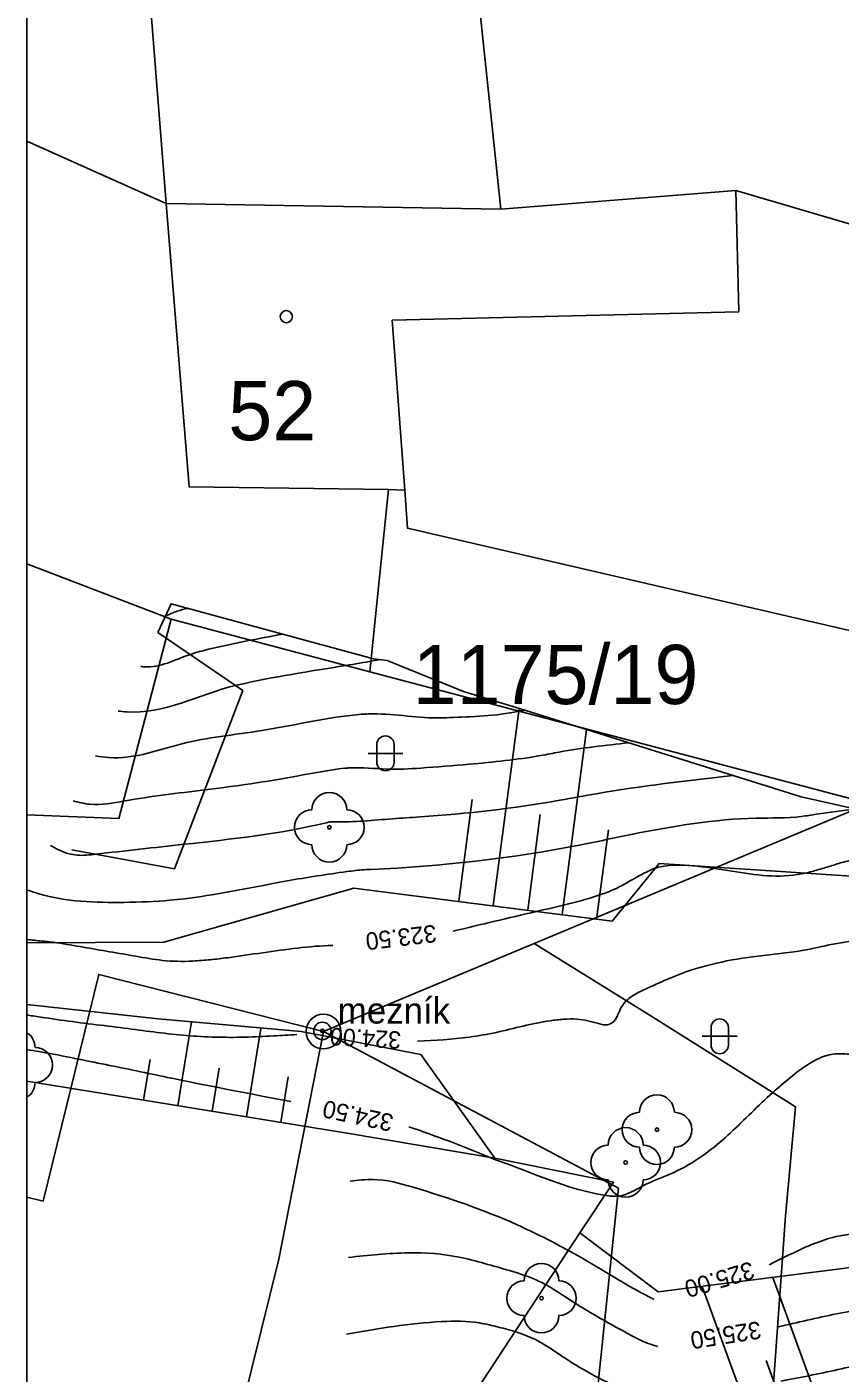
# Model space of a CAD drawing. Extents: x -564043 to -563833, y -1163561 to -1163412.
# Drawn here: x -564043.05 to -564019.66, y -1163509.03 to -1163470.35 of the extents above; entities that cross this region are included whole.
import ezdxf

# ---------------------------------------------------------------- set-up
doc = ezdxf.new("R2010")
doc.units = 0
for name, color, linetype in [('_rám PH1 a PH3', 7, 'Continuous'), ('Hranice parcel', 7, 'Continuous'), ('Parcelní čísla', 7, 'Continuous'), ('Vnitřní kresba', 7, 'Continuous'), ('Vrstva 14', 7, 'Continuous'), ('Vrstva 22', 7, 'Continuous'), ('Vrstva 24', 7, 'Continuous'), ('Vrstva 25', 7, 'Continuous'), ('Vrstva 26', 7, 'Continuous'), ('Vrstva 41', 7, 'Continuous'), ('Vrstva 48', 7, 'Continuous'), ('Značky bodu BP', 7, 'Continuous'), ('Značky budov', 7, 'Continuous')]:
    doc.layers.add(name, color=color, linetype=linetype)

msp = doc.modelspace()

# ---------------------------------------------------------------- linework, layer by layer
at = {"layer": '_rám PH1 a PH3'}
msp.add_line((-564043.046, -1163412.494), (-564043.046, -1163560.994), dxfattribs=at)
at = {"layer": 'Hranice parcel'}
for p, q in [((-564040.63, -1163455.19), (-564039.04, -1163475.43)), ((-564043.046, -1163473.637), (-564039.04, -1163475.43)), ((-564032.65, -1163483.65), (-564033.19, -1163488.88)), ((-564033.19, -1163488.88), (-564038.9, -1163487.37)), ((-564018.83, -1163492.67), (-564033.19, -1163488.88)), ((-564028.46, -1163496.69), (-564018.83, -1163492.67)), ((-564034.52, -1163499.22), (-564028.46, -1163496.69))]:
    msp.add_line(p, q, dxfattribs=at)
for points in [[(-564039.04, -1163475.43), (-564029.42, -1163475.59), (-564022.66, -1163475.05), (-564001.49, -1163481.27)], [(-564039.04, -1163475.43), (-564038.38, -1163483.57), (-564032.65, -1163483.65)], [(-564032.65, -1163483.65), (-564032.18, -1163483.66), (-564032.1, -1163484.76), (-564017.32, -1163488.18), (-564018.83, -1163492.67)], [(-564038.9, -1163487.37), (-564043.046, -1163485.784)], [(-564043.046, -1163492.996), (-564040.4, -1163493.1), (-564038.9, -1163487.37)], [(-564028.46, -1163496.69), (-564025.15, -1163498.74), (-564020.95, -1163501.38), (-564021.23, -1163504.52), (-564021.9, -1163513.74)], [(-564034.52, -1163499.22), (-564040.98, -1163497.58), (-564042.58, -1163504.09), (-564043.046, -1163503.975)], [(-564037.34, -1163511.95), (-564035.8, -1163505.76), (-564034.52, -1163499.22)], [(-564033.84, -1163535.6), (-564027.54, -1163518.14), (-564026.04, -1163503.72), (-564034.52, -1163499.22)]]:
    msp.add_lwpolyline(points, dxfattribs=at)
at = {"layer": 'Vnitřní kresba'}
for p, q in [((-564030.92, -1163461.24), (-564029.42, -1163475.59)), ((-564022.58, -1163478.54), (-564022.66, -1163475.05)), ((-564032.54, -1163478.78), (-564022.58, -1163478.54)), ((-564032.54, -1163478.78), (-564032.18, -1163483.66))]:
    msp.add_line(p, q, dxfattribs=at)
at = {"layer": 'Vrstva 14'}
for points in [[(-564033.08, -1163488.51), (-564038.9, -1163486.93), (-564039.28, -1163487.75)], [(-564039.28, -1163487.75), (-564036.84, -1163489.42), (-564038.8, -1163494.54), (-564041.75, -1163494)], [(-564032.69, -1163488.56), (-564033.08, -1163488.51)], [(-564005.7, -1163491.6), (-564006.2, -1163491.58), (-564012.27, -1163492.36), (-564018.09, -1163493.08), (-564020.78, -1163492.48), (-564028.85, -1163489.95), (-564030.49, -1163489.45), (-564032.69, -1163488.56)], [(-564027.15, -1163505), (-564024.9, -1163506.7), (-564019.59, -1163506.03), (-564017.25, -1163505.67), (-564014.46, -1163504.32), (-564008.13, -1163500.82), (-564005.74, -1163499.66), (-563997.05, -1163495.87), (-563995.48, -1163492.66)], [(-564043.046, -1163496.675), (-564039.11, -1163496.65), (-564033.65, -1163495.1), (-564026.22, -1163496.05), (-564024.87, -1163494.39), (-564018.75, -1163494.79), (-564015.5, -1163495.09), (-564011.97, -1163494.31)], [(-564043.046, -1163498.44), (-564039.27, -1163498.85), (-564035.16, -1163499.22), (-564031.72, -1163499.88), (-564029.59, -1163502.86)], [(-564043.046, -1163500.646), (-564033.72, -1163502.16), (-564029.59, -1163502.86), (-564026.18, -1163503.55), (-564027.15, -1163505), (-564030.15, -1163509.57), (-564034.03, -1163515.15), (-564041.74, -1163526.9)]]:
    msp.add_lwpolyline(points, dxfattribs=at)
at = {"layer": 'Vrstva 22'}
for centre in [(-564034.35, -1163493.35), (-564024.93, -1163502.04), (-564025.83, -1163502.98), (-564028.25, -1163506.88)]:
    msp.add_circle(centre, 0.05, dxfattribs=at)
for centre, start, end in [((-564034.35, -1163492.85), 0, 180), ((-564034.85, -1163493.35), 90, 270), ((-564033.85, -1163493.35), 270, 90), ((-564034.35, -1163493.85), 180, 0), ((-564043.31, -1163499.68), 0, 58.0739), ((-564042.81, -1163500.18), 270, 90), ((-564043.31, -1163500.68), 301.9261, 0), ((-564024.93, -1163501.54), 0, 180), ((-564025.43, -1163502.04), 90, 270), ((-564024.43, -1163502.04), 270, 90), ((-564025.83, -1163502.48), 0, 180), ((-564026.33, -1163502.98), 90, 270), ((-564024.93, -1163502.54), 180, 0), ((-564025.33, -1163502.98), 270, 90), ((-564025.83, -1163503.48), 180, 0), ((-564028.25, -1163506.38), 0, 180), ((-564028.75, -1163506.88), 90, 270), ((-564027.75, -1163506.88), 270, 90), ((-564028.25, -1163507.38), 180, 0)]:
    msp.add_arc(centre, 0.5, start, end, dxfattribs=at)
at = {"layer": 'Vrstva 24'}
for radius in [0.25, 0.05]:
    msp.add_circle((-564034.55, -1163499.2), radius, dxfattribs=at)
for points in [[(-564040.42, -1163490.01), (-564040.184, -1163490.036), (-564037.051, -1163489.276), (-564036.974, -1163489.258), (-564033.879, -1163488.703), (-564033.095, -1163488.569), (-564032.88, -1163488.53)], [(-564041.72, -1163492.59), (-564041.232, -1163492.69), (-564040.244, -1163492.595), (-564037.934, -1163492.277), (-564035.281, -1163491.88), (-564033.905, -1163491.655), (-564033.758, -1163491.643), (-564032.696, -1163491.679), (-564031.72, -1163491.649), (-564030.331, -1163491.539), (-564028.273, -1163491.289), (-564027.738, -1163491.19), (-564025.74, -1163490.92)], [(-564043.01, -1163495.16), (-564042.704, -1163495.259), (-564040.249, -1163495.507), (-564038.933, -1163495.447), (-564035.565, -1163494.892), (-564033.841, -1163494.623), (-564033.354, -1163494.57), (-564033.147, -1163494.56), (-564027.164, -1163493.861), (-564025.624, -1163493.548), (-564022.084, -1163493.089), (-564020.777, -1163493.039), (-564020.345, -1163492.975), (-564019.205, -1163492.831), (-564014.698, -1163492.66), (-564013.156, -1163492.656), (-564012.231, -1163492.615), (-564007.86, -1163491.79)], [(-564031.812, -1163499.5), (-564030.324, -1163499.377), (-564029.547, -1163499.242), (-564028.773, -1163499.061), (-564028.001, -1163498.908), (-564027.615, -1163498.867), (-564027.23, -1163498.862), (-564026.607, -1163498.989), (-564026.346, -1163499.024), (-564026.173, -1163498.931), (-564026.053, -1163498.733), (-564025.945, -1163498.506), (-564025.804, -1163498.324), (-564025.519, -1163498.129), (-564024.955, -1163497.86), (-564024.387, -1163497.614), (-564023.213, -1163497.254), (-564022.022, -1163497.051), (-564020.757, -1163496.892), (-564019.862, -1163496.708), (-564018.98, -1163496.594), (-564018.537, -1163496.592), (-564018.102, -1163496.651), (-564017.139, -1163496.933), (-564016.188, -1163497.257), (-564015.239, -1163497.589), (-564014.283, -1163497.894), (-564013.587, -1163498.092), (-564013.3, -1163498.155), (-564013.009, -1163498.205), (-564012.719, -1163498.253), (-564012.43, -1163498.312), (-564010.133, -1163499.025), (-564009.7, -1163499.224), (-564009.288, -1163499.466), (-564008.873, -1163499.71), (-564008.431, -1163499.916), (-564006.88, -1163500.213), (-564005.699, -1163500.108), (-564005.367, -1163500.004), (-564005.352, -1163499.957), (-564005.385, -1163499.904), (-564005.432, -1163499.847), (-564005.458, -1163499.79), (-564005.454, -1163499.732), (-564005.373, -1163499.663), (-564004.291, -1163498.6), (-564003.237, -1163497.506), (-564002.153, -1163496.417), (-564001.583, -1163495.886), (-564000.985, -1163495.371), (-564000.543, -1163495.196), (-564000.072, -1163495.171), (-563999.593, -1163495.223), (-563999.117, -1163495.267), (-563998.655, -1163495.218), (-563997.978, -1163494.98), (-563997.317, -1163494.68), (-563996.656, -1163494.38), (-563995.98, -1163494.14), (-563995.697, -1163494.069), (-563995.41, -1163494.016), (-563995.123, -1163493.963), (-563994.84, -1163493.89), (-563994.137, -1163493.61)], [(-564043.046, -1163498.746), (-564042.876, -1163498.771), (-564041.965, -1163498.904), (-564041.052, -1163499.022), (-564040.139, -1163499.136), (-564038.46, -1163499.333), (-564036.791, -1163499.381), (-564035.955, -1163499.345), (-564035.287, -1163499.307)], [(-564033.86, -1163507.91), (-564031.122, -1163507.553), (-564030.032, -1163507.592), (-564029.488, -1163507.711), (-564028.944, -1163507.863), (-564028.376, -1163508.095), (-564028.052, -1163508.286), (-564027.739, -1163508.492), (-564027.427, -1163508.7), (-564027.104, -1163508.896), (-564025.446, -1163509.596), (-564024.844, -1163509.663)], [(-564021.371, -1163509.263), (-564021.186, -1163509.229), (-564019.518, -1163508.884), (-564018.247, -1163508.582), (-564017.543, -1163508.388), (-564017.047, -1163508.212), (-564016.56, -1163508.013), (-564016.075, -1163507.809), (-564015.585, -1163507.616), (-564015.501, -1163507.589), (-564015.062, -1163507.521), (-564014.301, -1163507.825), (-564013.306, -1163508.208), (-564013.192, -1163508.237), (-564013.152, -1163508.254), (-564012.927, -1163508.404), (-564012.718, -1163508.577), (-564012.293, -1163508.914), (-564011.825, -1163509.22), (-564011.356, -1163509.532), (-564010.401, -1163510.124), (-564008.351, -1163510.852), (-564006.535, -1163511.003), (-564002.621, -1163511.374), (-564001.777, -1163511.54), (-564000.952, -1163511.799), (-564000.128, -1163512.073), (-563999.289, -1163512.284), (-563996.174, -1163512.66), (-563990.953, -1163512.711), (-563989.709, -1163512.624), (-563988.468, -1163512.494), (-563986.004, -1163512.066), (-563985.116, -1163511.837), (-563984.242, -1163511.579), (-563983.382, -1163511.285), (-563982.536, -1163510.951), (-563981.471, -1163510.495)]]:
    msp.add_spline(points, degree=3, dxfattribs=at)
at = {"layer": 'Vrstva 25'}
for p, q in [((-564032.986, -1163490.976), (-564032.986, -1163491.476)), ((-564032.486, -1163490.976), (-564032.486, -1163491.476)), ((-564033.236, -1163491.226), (-564032.236, -1163491.226)), ((-564023.376, -1163499.106), (-564023.376, -1163499.606)), ((-564022.876, -1163499.106), (-564022.876, -1163499.606)), ((-564023.626, -1163499.356), (-564022.626, -1163499.356))]:
    msp.add_line(p, q, dxfattribs=at)
for centre, start, end in [((-564032.736, -1163490.976), 0, 180), ((-564032.736, -1163491.476), 180, 0), ((-564023.126, -1163499.106), 0, 180), ((-564023.126, -1163499.606), 180, 0)]:
    msp.add_arc(centre, 0.25, start, end, dxfattribs=at)
for points in [[(-564039.06, -1163487.28), (-564038.725, -1163487.141), (-564038.41, -1163487.06)], [(-564021.704, -1163505.921), (-564021.679, -1163505.908), (-564021.057, -1163505.601), (-564020.425, -1163505.318), (-564019.55, -1163505.067), (-564019.102, -1163505.015), (-564018.672, -1163505.024), (-564018.428, -1163505.139), (-564018.218, -1163505.363), (-564018.005, -1163505.598), (-564017.748, -1163505.747), (-564017.265, -1163505.807), (-564017.147, -1163505.791), (-564014.765, -1163505.278), (-564013.855, -1163505.025), (-564011.755, -1163504.16), (-564009.388, -1163503.14), (-564008.683, -1163503.187), (-564008.113, -1163503.379), (-564007.551, -1163503.598), (-564006.987, -1163503.811), (-564006.412, -1163503.982), (-564005.323, -1163504.224), (-564003.629, -1163504.674), (-564003.259, -1163504.818), (-564002.04, -1163505.119), (-564001.419, -1163505.147), (-564000.82, -1163505.047), (-564000.232, -1163504.846), (-563999.668, -1163504.61), (-563998.596, -1163504.017), (-563996.597, -1163502.522), (-563996.542, -1163502.471), (-563996.497, -1163502.435), (-563996.203, -1163502.3), (-563995.993, -1163502.248), (-563990.872, -1163502.073), (-563988.998, -1163502), (-563988.338, -1163501.889), (-563985.154, -1163501.005), (-563982.47, -1163500.199)], [(-564033.75, -1163503.52), (-564033.09, -1163503.468), (-564031.943, -1163503.693), (-564028.953, -1163504.771), (-564027.455, -1163505.522), (-564026.417, -1163506.121), (-564025.381, -1163506.726), (-564025.017, -1163506.915)]]:
    msp.add_spline(points, degree=3, dxfattribs=at)
at = {"layer": 'Vrstva 26'}
for points in [[(-564039.77, -1163488.73), (-564039.671, -1163488.74), (-564038.352, -1163488.385), (-564037.82, -1163488.236), (-564035.69, -1163487.8)], [(-564030.787, -1163496.336), (-564028.401, -1163495.771), (-564026.55, -1163495.284), (-564026.147, -1163495.128), (-564025.763, -1163494.926), (-564025.381, -1163494.714), (-564024.983, -1163494.529), (-564024.778, -1163494.476), (-564023.777, -1163494.469), (-564022.768, -1163494.613), (-564021.761, -1163494.742), (-564020.768, -1163494.69), (-564020.378, -1163494.594), (-564019.992, -1163494.479), (-564019.605, -1163494.362), (-564019.215, -1163494.261), (-564018.494, -1163494.127), (-564018.03, -1163494.125), (-564017.565, -1163494.144), (-564016.635, -1163494.209), (-564015.486, -1163494.302), (-564014.546, -1163494.457), (-564013.618, -1163494.674), (-564013.287, -1163494.768), (-564012.961, -1163494.879), (-564012.635, -1163494.991), (-564012.302, -1163495.087), (-564011.185, -1163495.184), (-564010.325, -1163495.07), (-564009.466, -1163494.913), (-564008.615, -1163494.71), (-564007.775, -1163494.461), (-564005.875, -1163493.819), (-564004.998, -1163493.505), (-564003.872, -1163493.237), (-564002.608, -1163493.074), (-563997.404, -1163492.441), (-563996.84, -1163492.35), (-563996.277, -1163492.238), (-563995.433, -1163492.101), (-563995.293, -1163492.088), (-563995.152, -1163492.08), (-563994.744, -1163492.153), (-563994.067, -1163492.223), (-563993.74, -1163492.055), (-563993.078, -1163491.408), (-563992.901, -1163491.103), (-563992.782, -1163490.74), (-563992.679, -1163490.374), (-563992.526, -1163489.633), (-563992.48, -1163489.295), (-563992.41, -1163488.908)], [(-564041.07, -1163491.3), (-564040.702, -1163491.348), (-564038.446, -1163490.918), (-564037.338, -1163490.722), (-564036.127, -1163490.545), (-564033.5, -1163490.11), (-564033.221, -1163490.093), (-564031.239, -1163490.207), (-564030.908, -1163490.198), (-564028.91, -1163490.014), (-564028.829, -1163490), (-564028.806, -1163489.999), (-564028.73, -1163489.99)], [(-564042.37, -1163493.87), (-564041.834, -1163494.111), (-564041.598, -1163494.152), (-564041.067, -1163494.125), (-564038.532, -1163493.84), (-564034.433, -1163493.218), (-564034.309, -1163493.194), (-564034.195, -1163493.193), (-564032.535, -1163493.106), (-564031.742, -1163493.053), (-564027.719, -1163492.573), (-564026.667, -1163492.385), (-564022.75, -1163491.86)], [(-564043.046, -1163496.574), (-564042.613, -1163496.619), (-564042.397, -1163496.641), (-564042.182, -1163496.67), (-564041.424, -1163496.794), (-564040.667, -1163496.926), (-564039.909, -1163497.056), (-564039.148, -1163497.174), (-564038.274, -1163497.194), (-564038.022, -1163497.176), (-564037.771, -1163497.155), (-564037.519, -1163497.129), (-564037.269, -1163497.097), (-564036.266, -1163496.955), (-564035.262, -1163496.821), (-564034.254, -1163496.749), (-564034.245, -1163496.749)], [(-564043.046, -1163499.734), (-564042.339, -1163499.86), (-564041.447, -1163500.035), (-564040.557, -1163500.213), (-564038.778, -1163500.582), (-564035.461, -1163501.229)], [(-564032.062, -1163501.954), (-564029.752, -1163502.832), (-564029.575, -1163502.905), (-564029.515, -1163502.926), (-564026.43, -1163503.924), (-564026.019, -1163503.946), (-564025.314, -1163503.643), (-564024.556, -1163503.317), (-564023.709, -1163502.848), (-564023.05, -1163502.337), (-564022.439, -1163501.769), (-564021.838, -1163501.188), (-564021.209, -1163500.632), (-564020.733, -1163500.262), (-564020.476, -1163500.101), (-564020.197, -1163499.959), (-564019.747, -1163499.857), (-564019.293, -1163499.886), (-564017.758, -1163500.167), (-564016.239, -1163500.626), (-564015.064, -1163501.212), (-564014.816, -1163501.423), (-564014.602, -1163501.669), (-564014.388, -1163501.92), (-564014.134, -1163502.148), (-564013.542, -1163502.512), (-564013.225, -1163502.636), (-564012.894, -1163502.71), (-564012.546, -1163502.699), (-564012.199, -1163502.629), (-564011.502, -1163502.387), (-564010.8, -1163502.128), (-564010.087, -1163501.994), (-564009.248, -1163501.973), (-564008.411, -1163502.024), (-564008.151, -1163502.065), (-564007.892, -1163502.117), (-564007.634, -1163502.17), (-564007.375, -1163502.21), (-564006.906, -1163502.255), (-564006.434, -1163502.283), (-564005.962, -1163502.314), (-564005.493, -1163502.369), (-564003.875, -1163502.725), (-564003.078, -1163502.948), (-564002.283, -1163503.18), (-564002.242, -1163503.195), (-564001.98, -1163503.221), (-564001.075, -1163502.909), (-563999.457, -1163502.404), (-563998.647, -1163502.146), (-563998.242, -1163502.005), (-563998.039, -1163501.944), (-563997.939, -1163501.907), (-563997.838, -1163501.853), (-563997.785, -1163501.735), (-563998.108, -1163501.124), (-563998.377, -1163500.842), (-563998.693, -1163500.582), (-563999.025, -1163500.42), (-563999.386, -1163500.375), (-564000.04, -1163500.575), (-564000.222, -1163500.738), (-564000.381, -1163500.936), (-564000.542, -1163501.14), (-564000.728, -1163501.319), (-564001.452, -1163501.831), (-564001.829, -1163502.005), (-564002.013, -1163502.045), (-564002.192, -1163502.046), (-564002.617, -1163501.879), (-564003.007, -1163501.538), (-564003.361, -1163501.092), (-564003.68, -1163500.611), (-564003.715, -1163500.54)], [(-564021.468, -1163507.71), (-564021.242, -1163507.658), (-564020.402, -1163507.466), (-564019.558, -1163507.292), (-564018.974, -1163507.201), (-564018.579, -1163507.155), (-564018.183, -1163507.121), (-564017.395, -1163507.019), (-564016.324, -1163506.752), (-564015.131, -1163506.427), (-564013.124, -1163505.877), (-564011.958, -1163505.53), (-564011.372, -1163505.413), (-564011.082, -1163505.393), (-564010.939, -1163505.396), (-564010.796, -1163505.408), (-564010.707, -1163505.514), (-564010.652, -1163505.629), (-564010.617, -1163505.879), (-564010.626, -1163506.398), (-564010.641, -1163506.685), (-564010.632, -1163506.828), (-564010.586, -1163506.969), (-564010.46, -1163507.105), (-564010.333, -1163507.228), (-564010.076, -1163507.438), (-564009.553, -1163507.731), (-564009.025, -1163507.883), (-564008.499, -1163507.928), (-564007.844, -1163507.876), (-564007.186, -1163507.69), (-564006.53, -1163507.33), (-564006.203, -1163507.072), (-564006.04, -1163506.922), (-564005.877, -1163506.757), (-564005.786, -1163506.529), (-564005.801, -1163506.299), (-564005.847, -1163506.162), (-564005.934, -1163506.015), (-564005.993, -1163505.892), (-564005.951, -1163505.824), (-564005.87, -1163505.816), (-564005.789, -1163505.826), (-564005.625, -1163505.887), (-564005.294, -1163506.039), (-564005.154, -1163506.08), (-564004.954, -1163506.144), (-564004.272, -1163506.437), (-563998.752, -1163508.301), (-563998.369, -1163508.389), (-563996.721, -1163508.55), (-563995.072, -1163508.639), (-563991.772, -1163508.696), (-563989.868, -1163508.644), (-563988.87, -1163508.516), (-563987.881, -1163508.343), (-563985.925, -1163507.884), (-563984.065, -1163507.363)], [(-564033.8, -1163505.71), (-564032.074, -1163505.577), (-564030.613, -1163505.702), (-564029.889, -1163505.883), (-564029.168, -1163506.088), (-564028.429, -1163506.344), (-564028.048, -1163506.535), (-564027.562, -1163506.843), (-564026.408, -1163507.544), (-564025.812, -1163507.873), (-564025.179, -1163508.182), (-564024.906, -1163508.265)]]:
    msp.add_spline(points, degree=3, dxfattribs=at)
at = {"layer": 'Vrstva 48'}
for p, q in [((-564029.638, -1163495.6), (-564028.895, -1163489.936)), ((-564027.655, -1163495.86), (-564026.958, -1163490.546)), ((-564030.63, -1163495.47), (-564030.247, -1163492.55)), ((-564028.647, -1163495.73), (-564028.287, -1163492.986)), ((-564026.664, -1163495.99), (-564026.327, -1163493.421)), ((-564038.703, -1163501.35), (-564038.313, -1163498.94)), ((-564036.728, -1163501.669), (-564036.318, -1163499.128)), ((-564039.69, -1163501.19), (-564039.5, -1163500.018)), ((-564037.716, -1163501.509), (-564037.515, -1163500.272)), ((-564035.741, -1163501.829), (-564035.531, -1163500.525)), ((-564021.901, -1163511.276), (-564023.635, -1163506.54)), ((-564020.023, -1163510.589), (-564021.599, -1163506.283)), ((-564020.962, -1163510.932), (-564021.789, -1163508.672))]:
    msp.add_line(p, q, dxfattribs=at)
at = {"layer": 'Značky bodu BP'}
for radius in [0.5, 0.0303]:
    msp.add_circle((-564034.52, -1163499.22), radius, dxfattribs=at)
at = {"layer": 'Značky budov'}
msp.add_circle((-564035.587, -1163478.679), 0.175, dxfattribs=at)

# ---------------------------------------------------------------- texts
at = {"layer": 'Parcelní čísla'}
for s, p in [('52', (-564037.256, -1163482.23)), ('1175/19', (-564031.956, -1163489.81))]:
    msp.add_text(s, height=1.7, dxfattribs=at).set_placement(p)
at = {"layer": 'Vrstva 25'}
for s, rotation, p in [('323.50', 186.8068, (-564031.301, -1163496.146)), ('324.00', 176.826, (-564032.276, -1163499.221)), ('324.50', 167.8359, (-564032.476, -1163501.613)), ('325.00', 196.6676, (-564022.223, -1163505.814)), ('325.50', 188.943, (-564021.978, -1163507.538))]:
    msp.add_text(s, height=0.5, rotation=rotation, dxfattribs=at).set_placement(p)
at = {"layer": 'Vrstva 41'}
msp.add_text('mezník', height=0.75, dxfattribs=at).set_placement((-564034.11, -1163498.99))

doc.saveas('drawing.dxf')
